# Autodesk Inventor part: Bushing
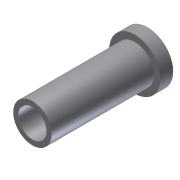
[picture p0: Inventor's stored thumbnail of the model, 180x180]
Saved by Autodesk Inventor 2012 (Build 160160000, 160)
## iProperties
Created: 2009-05
Part Number: Bushing
Document SubType Name: Modeling
Designer: Sham
Density: 1 g/cm^3
Material: Default
Author: Sham
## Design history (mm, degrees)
sketch "Sketch1"
  geometry: L1 (5.5, 6)-(10, 6); L2 (10, 6)-(10, 1); L3 (10, 1)-(7.5, 1); L4 (7.5, 1)-(7.5, -39); L5 (7.5, -39)-(5.5, -39); L6 (5.5, -39)-(5.5, 6); L7 (0, 0)-(0, -45)
  constraints: 14 end point, 6 perpendicular, 1 horizontal, 1 other
  dimensions: "d0" = 5 distance of L1.end L2.end; "d1" = 40 distance of L3.end L4.end; "d5" = 10 distance from line of L7.start L2; "d6" = 5.5 distance from line of L7.start L6; "d7" = 15 diameter of L4 L7
revolve "Revolution1" sketch "Sketch1" stored, may be unused: angle "d8" = 90 deg
body "Solid1"
